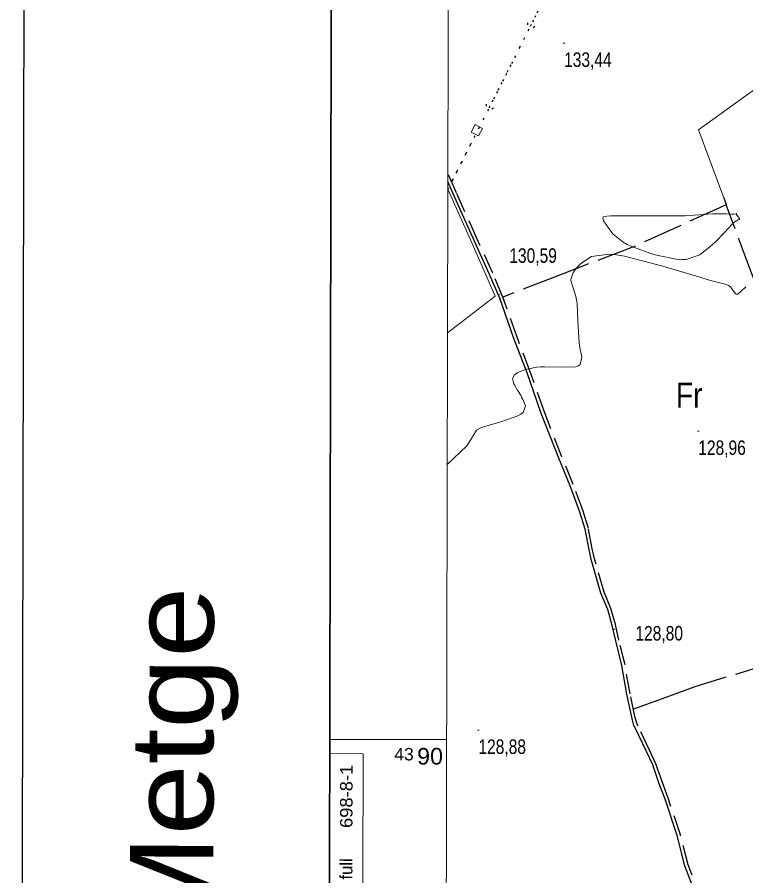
# Model space of a CAD drawing. Extents: x 483855 to 488461, y 4388206 to 4391419.
# Drawn here: x 483855 to 484293, y 4389918 to 4390435 of the extents above; entities that cross this region are included whole.
import ezdxf
from ezdxf.enums import TextEntityAlignment as Align

# ---------------------------------------------------------------- set-up
doc = ezdxf.new("R2010")
doc.units = 0
doc.header["$LTSCALE"] = 4
for name, pattern in [('DOTTED', [1.5, 0.3, -1.2]), ('LONG_DASHED', [7.5, 6, -1.5]), ('MEDIUM_DASHED', [4.5, 3, -1.5])]:
    doc.linetypes.add(name, pattern=pattern)
for name, color, linetype, lineweight in [('1', 7, 'Continuous', 13), ('2', 7, 'DOTTED', 13), ('25', 7, 'LONG_DASHED', 25), ('38', 7, 'Continuous', 25), ('43', 7, 'DOTTED', 25), ('51', 7, 'Continuous', 13), ('7', 7, 'Continuous', 13), ('9', 7, 'Continuous', 13)]:
    doc.layers.add(name, color=color, linetype=linetype, lineweight=lineweight)
doc.layers.add('31', color=7, linetype='Continuous')

msp = doc.modelspace()

# ---------------------------------------------------------------- linework, layer by layer
at = {"layer": '1'}
for p, q in [((484113.18, 4390000), (484042.85, 4390000)), ((484042.84, 4389991.59), (484062.84, 4389991.55))]:
    msp.add_line(p, q, dxfattribs=at)
at = {"layer": '1', "lineweight": 25}
msp.add_lwpolyline([(483860.86, 4391419.44), (488460.85, 4391410.69), (488454.76, 4388205.69), (483854.77, 4388214.44)], close=True, dxfattribs=at)
at = {"layer": '1', "lineweight": 35}
msp.add_lwpolyline([(484045.03, 4391144.08), (487760.33, 4391137.02), (487755.66, 4388682.02), (484040.36, 4388689.09)], close=True, dxfattribs=at)
at = {"layer": '1'}
msp.add_lwpolyline([(484115.5, 4391072.6), (487689.7, 4391065.7), (487685.8, 4388753.5), (484110.5, 4388760.3)], close=True, dxfattribs=at)
msp.add_lwpolyline([(484042.56, 4389841.59), (484062.56, 4389841.55), (484062.84, 4389991.55)], dxfattribs=at)
at = {"layer": '25'}
for points in [[(484279.92, 4390325.99), (484281.28, 4390321.92), (484226.52, 4390296.99), (484181.58, 4390279.75), (484147.03, 4390266.32)], [(484320.92, 4390223.97), (484312.2, 4390244.8), (484297.26, 4390279.36), (484281.28, 4390321.92)], [(484380.2, 4390077.77), (484357, 4390067.81), (484309.8, 4390046.3), (484262.56, 4390031.83), (484242.84, 4390024.6), (484225.52, 4390018.43)]]:
    msp.add_lwpolyline(points, dxfattribs=at)
at = {"layer": '38', "linetype": 'MEDIUM_DASHED'}
msp.add_lwpolyline([(484267.15, 4389901.67), (484258.45, 4389924.72), (484253.79, 4389942.79), (484246.43, 4389964.74), (484242.99, 4389974.12), (484239.02, 4389985.52), (484235.12, 4389993.75), (484228.37, 4390008.09), (484227.7, 4390009.22), (484226.45, 4390013.98), (484223.6, 4390027.65), (484220.47, 4390044.95), (484216.85, 4390059.83), (484214.73, 4390069.27), (484211.99, 4390079.01), (484207.89, 4390088.78), (484203.05, 4390105.61), (484202.07, 4390108.86), (484200.8, 4390114.92), (484198.49, 4390127.12), (484195.01, 4390138.13), (484189.36, 4390153.55), (484182.51, 4390170.23), (484171.74, 4390197.64), (484163.44, 4390221.36), (484155.53, 4390242.14), (484147.03, 4390266.32), (484140.85, 4390280.79), (484131.5, 4390301.16), (484119.13, 4390328.97), (484113.92, 4390340.84)], dxfattribs=at)
at = {"layer": '38'}
msp.add_lwpolyline([(484265.25, 4389901.03), (484256.53, 4389924.11), (484251.87, 4389942.22), (484244.54, 4389964.08), (484241.1, 4389973.45), (484237.16, 4389984.76), (484233.31, 4389992.9), (484226.6, 4390007.15), (484225.83, 4390008.44), (484224.49, 4390013.52), (484221.63, 4390027.27), (484218.51, 4390044.53), (484214.89, 4390059.37), (484212.78, 4390068.78), (484210.09, 4390078.34), (484205.99, 4390088.12), (484201.13, 4390105.04), (484200.12, 4390108.36), (484198.83, 4390114.52), (484196.54, 4390126.63), (484193.11, 4390137.48), (484187.49, 4390152.82), (484180.65, 4390169.48), (484169.86, 4390196.94), (484161.56, 4390220.67), (484153.65, 4390241.45), (484145.16, 4390265.59), (484139.01, 4390279.97), (484129.67, 4390300.34), (484117.29, 4390328.16), (484113.91, 4390335.9)], dxfattribs=at)
at = {"layer": '43'}
for p, q in [((484252.08, 4390604.26), (484113.96, 4390331.46)), ((484177.55, 4390457.05), (484161.74, 4390425.83)), ((484161.77, 4390431.42), (484161.74, 4390425.83)), ((484166.23, 4390429.16), (484161.74, 4390425.83)), ((484157.45, 4390417.35), (484157, 4390416.46)), ((484152.7, 4390407.98), (484136.89, 4390376.76)), ((484136.92, 4390382.35), (484136.89, 4390376.76)), ((484141.38, 4390380.09), (484136.89, 4390376.76)), ((484132.6, 4390368.28), (484132.15, 4390367.39)), ((484127.86, 4390358.91), (484113.96, 4390331.46))]:
    msp.add_line(p, q, dxfattribs=at)
at = {"layer": '43', "linetype": 'Continuous', "lineweight": 13}
msp.add_lwpolyline([(484132.39, 4390363.36), (484127.95, 4390365.66), (484130.25, 4390370.1), (484134.69, 4390367.8)], close=True, dxfattribs=at)
at = {"layer": '51'}
for points in [[(484314.22, 4390402.75), (484264.72, 4390367.03), (484279.92, 4390325.99)], [(484113.71, 4390244.78), (484142.26, 4390266.86), (484128.49, 4390298.52), (484113.9, 4390331.18)]]:
    msp.add_lwpolyline(points, dxfattribs=at)
at = {"layer": '7'}
for p, q in [((484183.32, 4390419.21), (484184.32, 4390419.21)), ((484143.93, 4390268.14), (484144.93, 4390268.14)), ((484264.04, 4390185.68), (484265.04, 4390185.68)), ((484213.39, 4390066.53), (484214.39, 4390066.53)), ((484131.76, 4390005.78), (484132.76, 4390005.78))]:
    msp.add_line(p, q, dxfattribs=at)
at = {"layer": '9'}
msp.add_lwpolyline([(484256.59, 4390315.22), (484232.49, 4390315.3), (484217.18, 4390315.26), (484214.2, 4390315.21), (484211.77, 4390315.15), (484207.54, 4390314.78), (484207.15, 4390314.1), (484207.14, 4390313.85), (484207.16, 4390313.56), (484207.59, 4390312.27), (484208.89, 4390310.13), (484209.46, 4390309.3), (484210.13, 4390308.38), (484213.29, 4390304.19), (484219.32, 4390299.37), (484221.79, 4390298.04), (484224.6, 4390296.72), (484237.64, 4390291.96), (484251.22, 4390289.07), (484254.38, 4390288.91), (484257.26, 4390289.04), (484265.5, 4390291.85), (484271.73, 4390296.72), (484273.36, 4390298.16), (484274.95, 4390299.62), (484280.32, 4390305.23), (484284.68, 4390309.93), (484285.62, 4390310.83), (484286.45, 4390311.56), (484288.5, 4390312.75), (484289.32, 4390313.02), (484289.39, 4390313.18), (484289.38, 4390313.37), (484288.73, 4390314.36), (484287.88, 4390315.41), (484287.74, 4390315.64), (484287.64, 4390315.85), (484287.63, 4390316.39), (484287.74, 4390316.63), (484287.72, 4390316.65), (484287.68, 4390316.64), (484287.36, 4390316.45), (484286.14, 4390316.24), (484285.54, 4390316.23), (484284.82, 4390316.23), (484281.27, 4390316.41), (484276.34, 4390316.53), (484274.75, 4390316.5), (484273.06, 4390316.44)], close=True, dxfattribs=at)
msp.add_lwpolyline([(484293.22, 4390272.47), (484290.27, 4390269.96), (484288.38, 4390268), (484287.87, 4390267.9), (484287.38, 4390267.99), (484285.69, 4390269.89), (484283.93, 4390272.46), (484283.41, 4390272.96), (484282.86, 4390273.38), (484280.71, 4390274.15), (484273.6, 4390275.93), (484269.91, 4390276.98), (484265.48, 4390278.28), (484243.3, 4390284.98), (484220.25, 4390290.9), (484215.28, 4390291.7), (484210.92, 4390292.13), (484200.26, 4390290.67), (484194.51, 4390286.88), (484193.24, 4390285.85), (484192.11, 4390284.83), (484189.2, 4390281.21), (484187.99, 4390277.61), (484187.94, 4390276.6), (484188.01, 4390275.59), (484189.26, 4390271.9), (484190.96, 4390266.62), (484191.3, 4390264.61), (484191.59, 4390262.36), (484192.18, 4390252.24), (484192.68, 4390241.74), (484192.9, 4390239.25), (484193.17, 4390236.94), (484194.45, 4390230.09), (484193.51, 4390225.71), (484192.38, 4390224.96), (484190.86, 4390224.41), (484182.23, 4390224.06), (484172.12, 4390224.43), (484169.68, 4390224.33), (484167.39, 4390224.13), (484160.4, 4390222.7), (484155.6, 4390220.66), (484154.69, 4390220.09), (484153.96, 4390219.51), (484152.82, 4390217.37), (484153.31, 4390214.97), (484153.6, 4390214.22), (484153.95, 4390213.44), (484155.81, 4390210.31), (484157.95, 4390206.81), (484158.48, 4390205.79), (484158.99, 4390204.75), (484160.61, 4390200.81), (484159.22, 4390196.88), (484157.83, 4390195.84), (484156.01, 4390194.83), (484145.79, 4390191.35), (484135.3, 4390188.27), (484133.3, 4390187.5), (484131.04, 4390186.2), (484129.04, 4390182.92), (484125.21, 4390176.89), (484113.54, 4390165.59)], dxfattribs=at)

# ---------------------------------------------------------------- texts
at = {"layer": '2', "width": 1.15}
msp.add_text('Cas Metge ', height=50, rotation=89.876, dxfattribs=at).set_placement((483972.69, 4389916.78), align=Align.CENTER)
at = {"layer": '2', "width": 1.05}
for s, height, p in [('43', 7.5, (484093.38, 4389987.5)), ('90', 10, (484110.98, 4389985))]:
    msp.add_text(s, height=height, dxfattribs=at).set_placement(p, align=Align.RIGHT)
at = {"layer": '2', "width": 1.1}
msp.add_text('698-8-1', height=7.5, rotation=89.891, dxfattribs=at).set_placement((484056.51, 4389946.81))
at = {"layer": '2'}
msp.add_text('Enlla/a amb el full', height=7.5, rotation=89.891, dxfattribs=at).set_placement((484056.32, 4389849.44))
at = {"layer": '31', "width": 0.85}
msp.add_text('Fr', height=15, dxfattribs=at).set_placement((484259.11, 4390199.86), align=Align.CENTER)
at = {"layer": '7', "width": 0.8}
for s, p in [('133,44', (484183.82, 4390404.84)), ('130,59', (484150.85, 4390286.93)), ('128,96', (484264.54, 4390171.31)), ('128,80', (484226.72, 4390059.65)), ('128,88', (484132.26, 4389991.41))]:
    msp.add_text(s, height=8.75, dxfattribs=at).set_placement(p)

doc.saveas('drawing.dxf')
